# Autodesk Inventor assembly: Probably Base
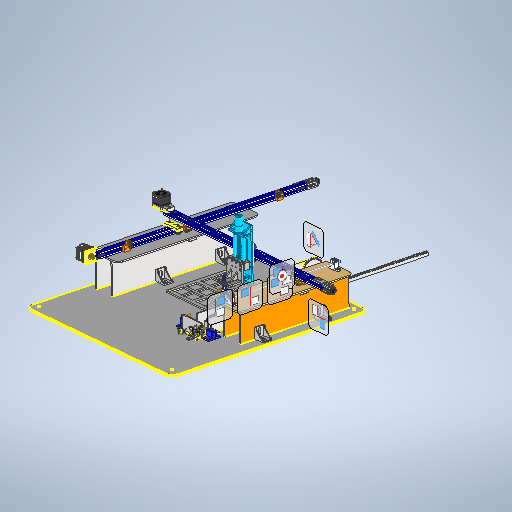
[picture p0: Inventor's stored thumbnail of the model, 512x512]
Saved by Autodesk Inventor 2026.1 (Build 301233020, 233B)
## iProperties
Created: 2026-10
Part Number: Probably Base
Document SubType Name: Assembly
Designer: hp
Author: hp
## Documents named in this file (53)
- C:\Users\hp\Documents\Inventor\DOM1_CartesianRobot\Probably Base.iam
- C:\Users\hp\Documents\Inventor\DOM1_CartesianRobot\StorageArea.ipt
- C:\Users\hp\Documents\Inventor\DOM1_CartesianRobot\BigBase.ipt
- C:\Users\hp\Documents\Inventor\DOM1_CartesianRobot\Side Wall Support.ipt
- C:\Users\hp\Documents\Inventor\DOM1_CartesianRobot\Belt Support.ipt
- C:\Users\hp\Documents\Inventor\DOM1_CartesianRobot\Assieme_guida_2020_nema.iam
- C:\Users\hp\Documents\Inventor\DOM1_CartesianRobot\Assieme_guida_2020_nema - Copy.iam
- C:\Users\hp\Documents\Inventor\DOM1_CartesianRobot\aluminum rod.ipt
- C:\Users\hp\Documents\Inventor\DOM1_CartesianRobot\color_sensor_holder.iam
- C:\Users\hp\Documents\Inventor\DOM1_CartesianRobot\reciever_wall.ipt
- C:\Users\hp\Documents\Inventor\DOM1_CartesianRobot\laser_assembly.iam
- C:\Users\hp\Documents\Inventor\DOM1_CartesianRobot\laser_detector.iam
- C:\Users\hp\Documents\Inventor\DOM1_CartesianRobot\piatto.ipt
- C:\Users\hp\Documents\Inventor\DOM1_CartesianRobot\z axis screw.iam
- C:\Users\hp\Documents\Inventor\DOM1_CartesianRobot\z_Bearing_Housing_Assembly.iam
- C:\Users\hp\Documents\Inventor\DOM1_CartesianRobot\tool_mout_assembly.iam
- C:\Users\hp\Documents\Inventor\DOM1_CartesianRobot\Side Wall Support 2.ipt
- C:\Users\hp\Documents\Inventor\DOM1_CartesianRobot\filler.ipt
- C:\Users\hp\Documents\Inventor\DOM1_CartesianRobot\L-Bracket.ipt
- C:\Users\hp\Documents\Inventor\DOM1_CartesianRobot\Belt Support_v2.ipt
- C:\Users\hp\Documents\Inventor\DOM1_CartesianRobot\8mm_Railclamp.ipt
- C:\Users\hp\Documents\Inventor\DOM1_CartesianRobot\SC8UU Linear Rail Bearing v5.ipt
- C:\Users\hp\Documents\Inventor\Content Center Files\R2026\en-US\ISO 4762(2)\ISO 4762 - M5 x 20ISO.ipt
- C:\Users\hp\Documents\Inventor\Content Center Files\R2026\en-US\ISO 7041\ISO 7041 - M5 - ISO.ipt
- C:\Users\hp\Documents\Inventor\DOM1_CartesianRobot\4040 Corner Bracket Right Angle L Shape.ipt
- C:\Users\hp\Documents\Inventor\Content Center Files\R2026\en-US\ISO 4762(2)\ISO 4762 - M6 x 20ISO.ipt
- C:\Users\hp\Documents\Inventor\Content Center Files\R2026\en-US\ISO 7041\ISO 7041 - M6 - ISO.ipt
- C:\Users\hp\Documents\Inventor\Content Center Files\R2026\en-US\JIS B 1111(2)\JIS B 1111 - M3x40(2).ipt
- C:\Users\hp\Documents\Inventor\DOM1_CartesianRobot\2020 M3.ipt
- C:\Users\hp\Documents\Inventor\Content Center Files\R2026\en-US\ISO 4017(1)\ISO 4017 - M4 x 35 - ISO.ipt
- C:\Users\hp\Documents\Inventor\DOM1_CartesianRobot\2020 M4 (1).ipt
- C:\Users\hp\Documents\Inventor\Content Center Files\R2026\en-US\ISO 4032(2)\ISO 4032 - M4 - ISO.ipt
- C:\Users\hp\Documents\Inventor\DOM1_CartesianRobot\Side Wall Support_v1_B.ipt
- C:\Users\hp\Documents\Inventor\DOM1_CartesianRobot\Side Wall Support 2 (B).ipt
- C:\Users\hp\Documents\Inventor\Content Center Files\R2026\en-US\ISO 4035(2)\ISO 4035 - M4 - ISO.ipt
- C:\Users\hp\Documents\Inventor\DOM1_CartesianRobot\color_sensor_holder_top.ipt
- C:\Users\hp\Documents\Inventor\DOM1_CartesianRobot\L298N Motor Driver.iam
- C:\Users\hp\Documents\Inventor\DOM1_CartesianRobot\Feeder Side Wall.ipt
- C:\Users\hp\Documents\Inventor\DOM1_CartesianRobot\pusher_support.ipt
- C:\Users\hp\Documents\Inventor\DOM1_CartesianRobot\pusher_pinion.ipt
- C:\Users\hp\Documents\Inventor\DOM1_CartesianRobot\pusher_punch.ipt
- C:\Users\hp\Documents\Inventor\DOM1_CartesianRobot\feeder_rack.ipt
- C:\Users\hp\Documents\Inventor\DOM1_CartesianRobot\Control Box.iam
- C:\Users\hp\Documents\Inventor\DOM1_CartesianRobot\NewProject\Product\Base.ipt
- C:\Users\hp\Documents\Inventor\DOM1_CartesianRobot\NewProject\Product\Lid.ipt
- C:\Users\hp\Documents\Inventor\DOM1_CartesianRobot\L-Bracket_3gneh.ipt
- C:\Users\hp\Documents\Inventor\Content Center Files\R2026\en-US\ISO 7045  H\ISO 7045 - M4 x 14_ - 4.8 - H - ISO.ipt
- C:\Users\hp\Documents\Inventor\DOM1_CartesianRobot\ColorSensorBottomPlate.ipt
- C:\Users\hp\Documents\Inventor\Content Center Files\R2026\en-US\ISO 7045  H\ISO 7045 - M4 x 35_ - 4.8 - H - ISO.ipt
- C:\Users\hp\Documents\Inventor\Content Center Files\R2026\en-US\ISO 7091\ISO 7091 - ST 4 - 100 HV.ipt
- C:\Users\hp\Documents\Inventor\DOM1_CartesianRobot\DC Motor Gearbox\DC Motor Gearbox\DC Motor Gearbox.iam
- C:\Users\hp\Documents\Inventor\Content Center Files\R2026\en-US\ISO 7045  H\ISO 7045 - M3 x 4_ - 4.8 - H - ISO.ipt
- C:\Users\hp\Documents\Inventor\Content Center Files\R2026\en-US\ISO 4035(2)\ISO 4035 - M3 - ISO.ipt
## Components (106 placed, 52 different names)
1. StorageArea:1 — Mate:1, Mate:690, Mate:691
2. BigBase:1 — Mate:1, Flush:17, Mate:40, Mate:41, Flush:22, Mate:62, Mate:64, Flush:23, Mate:66, Mate:67, Flush:24, Mate:70, Flush:27, Mate:119, Mate:121, Mate:123, Mate:125, Mate:132, Mate:133, Mate:134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
3. Assieme_guida_2020_nema:1 [sub-assembly] — Flush:9, Slider:1, Mate:75, Mate:76
4. Side Wall Support:1 — Mate:16, Flush:5, Flush:22, Mate:62, Mate:118, Mate:120, Mate:122, Mate:124, Mate:182, Flush:41, Mate:696
5. Side Wall Support_v1_B:1 — Mate:64, Flush:23, Flush:32, Mate:130, Mate:131, Mate:136, Mate:137, Mate:186, Mate:697
6. Belt Support:1 — Mate:16, Flush:5, Flush:9, Mate:75, Mate:76, Flush:32, Mate:183, Mate:188
7. Belt Support_v2:1 — Mate:68, Flush:25, Mate:91, Flush:35, Mate:92, Flush:36, Flush:37, Angle:1, Mate:192, Mate:196, Flush:62
8. Assieme_guida_2020_nema - Copy:1 [sub-assembly] — Mate:50, Slider:2, Mate:52, Flush:33, Flush:39, Mate:166, Mate:167, Angle:2, Angle:3, Mate:174, Mate:175, Angle:4, Angle:5
9. color_sensor_holder:1 [sub-assembly] — Mate:829, Flush:84, Flush:85, Flush:86
10. reciever_wall:1 — Flush:17, Mate:786, Flush:81, Mate:807, Mate:809, Mate:810, Mate:811
11. laser_assembly:1 [sub-assembly]
12. laser_detector:1 [sub-assembly] — Mate:41, Flush:82, Mate:811, Mate:816, Mate:818, Mate:824, Mate:826
13. piatto:1 — Slider:1, Mate:50, Mate:52, Mate:79, Flush:30, Flush:31, Mate:171, Mate:173
14. piatto:2 — Mate:48, Slider:2, Mate:71, Mate:72, Mate:117, Mate:161
15. z_Bearing_Housing_Assembly:1 [sub-assembly] — Mate:54, Mate:55, Mate:56, Mate:73, Mate:74, Mate:538, Mate:546, Mate:547, Mate:549, Mate:551, Mate:553
16. tool_mout_assembly:1 [sub-assembly] — Mate:54, Mate:55, Mate:56, Mate:539, Mate:540, Mate:541, Mate:542, Mate:543, Mate:544, Mate:545, Mate:548, Mate:550, Mate:552
17. Side Wall Support 2:1 — Mate:66, Mate:67, Flush:24, Mate:68, Flush:25, Mate:141, Mate:142, Mate:144, Mate:147, Mate:190, Flush:62, Flush:63
18. Side Wall Support 2 (B):1 — Mate:70, Flush:27, Mate:150, Mate:151, Mate:155, Mate:157, Mate:194, Flush:64, Mate:698
19. filler:1 — Mate:79, Flush:30, Flush:31, Flush:33, Mate:170, Mate:172
20. 8mm_Railclamp:1 — Mate:91, Flush:35, Mate:93, Flush:36, Mate:94, Flush:38
21. 8mm_Railclamp:2 — Mate:92, Mate:93, Flush:37
22. aluminum rod:1 — Mate:94, Flush:38, Mate:95
23. SC8UU Linear Rail Bearing v5:1 — Mate:95, Angle:1, Flush:39, Mate:162, Mate:163, Mate:164, Mate:165
24. ISO 4762 M5 x 20:1 — Mate:114, Mate:115
25. ISO 7041 M5:1 — Mate:116, Mate:117
26. 4040 Corner Bracket Right Angle L Shape:1 — Mate:118, Mate:119, Mate:126, Mate:178
27. 4040 Corner Bracket Right Angle L Shape:2 — Mate:120, Mate:121, Mate:127, Mate:178, Mate:694
28. 4040 Corner Bracket Right Angle L Shape:3 — Mate:122, Mate:123, Mate:126
29. 4040 Corner Bracket Right Angle L Shape:4 — Mate:124, Mate:125, Mate:127
30. 4040 Corner Bracket Right Angle L Shape:5 — Mate:135, Mate:137
31. 4040 Corner Bracket Right Angle L Shape:6 — Mate:134, Mate:136, Mate:179, Mate:695
32. 4040 Corner Bracket Right Angle L Shape:7 — Mate:130, Mate:133
33. 4040 Corner Bracket Right Angle L Shape:8 — Mate:131, Mate:132, Mate:179
34. 4040 Corner Bracket Right Angle L Shape:9 — Mate:140, Mate:141
35. 4040 Corner Bracket Right Angle L Shape:10 — Mate:142, Mate:143, Mate:180
36. 4040 Corner Bracket Right Angle L Shape:11 — Mate:144, Mate:145
37. 4040 Corner Bracket Right Angle L Shape:12 — Mate:146, Mate:147, Mate:180, Flush:63, Mate:694
38. 4040 Corner Bracket Right Angle L Shape:13 — Mate:154, Mate:155, Mate:181, Flush:64, Mate:695
39. 4040 Corner Bracket Right Angle L Shape:14 — Mate:156, Mate:157
40. 4040 Corner Bracket Right Angle L Shape:15 — Mate:150, Mate:153, Mate:181
41. 4040 Corner Bracket Right Angle L Shape:16 — Mate:151, Mate:152
42. ISO 4762 M6 x 20:1 — Mate:158, Mate:159
43. ISO 7041 M6:1 — Mate:160, Mate:161
44. JIS B 1111 M3x40:1 — Mate:162, Mate:163, Mate:168
45. JIS B 1111 M3x40:2 — Mate:164, Mate:165, Mate:169
46. 2020 M3:1 — Mate:166, Angle:2, Mate:168
47. 2020 M3:2 — Mate:167, Angle:3, Mate:169
48. ISO 4017 M4 x 35:1 — Mate:170, Mate:171, Mate:176
49. ISO 4017 M4 x 35:2 — Mate:172, Mate:173, Mate:177
50. 2020 M4 (1):1 — Mate:174, Angle:4, Mate:176
51. 2020 M4 (1):2 — Mate:175, Angle:5, Mate:177
52. L-Bracket:5 — Mate:182, Mate:183, Mate:200, Flush:41
53. L-Bracket:8 — Mate:194, Mate:196, Mate:199, Mate:203
54. L-Bracket:10 — Mate:190, Mate:192, Mate:199
55. L-Bracket:12 — Mate:186, Mate:188, Mate:200, Mate:203
56. ISO 4017 M4 x 35:3 — Mate:538, Mate:539
57. ISO 4035 M4:1 — Mate:546, Mate:547
58. ISO 4017 M4 x 35:4 — Mate:540, Mate:541
59. ISO 4017 M4 x 35:5 — Mate:542, Mate:543
60. ISO 4017 M4 x 35:6 — Mate:544, Mate:545
61. ISO 4035 M4:2 — Mate:548, Mate:549
62. ISO 4035 M4:3 — Mate:550, Mate:551
63. ISO 4035 M4:4 — Mate:552, Mate:553
64. color_sensor_holder_top:1 — Mate:651, Mate:652, Mate:786, Flush:86, Flush:87, Flush:88
65. L298N Motor Driver:1 [sub-assembly]
66. Feeder Side Wall:1 — Mate:707, Mate:710, Mate:712, Mate:799, Mate:800, Mate:801, Mate:802
67. Feeder Side Wall:2 — Mate:708, Mate:709, Mate:711, Mate:795, Mate:798, Mate:803, Mate:804
68. pusher_punch:2 — Mate:772, Mate:773, Mate:774, Flush:77
69. pusher_support:2 — Mate:847, Mate:848, Flush:90, Angle:6, Mate:856, Mate:858
70. pusher_pinion:2 — Flush:69, Mate:848, Mate:849, Mate:850, Flush:89
71. feeder_rack:1 — Mate:771, Flush:69, Mate:772, Mate:774, Flush:77, Flush:83
72. Control Box:1 [sub-assembly] — Mate:788
73. Base:1 — Mate:790
74. Lid:1 — Mate:789
75. L-Bracket_3gneh:1 — Mate:803, Mate:804
76. L-Bracket_3gneh:2 — Mate:801, Mate:802
77. L-Bracket_3gneh:4 — Mate:795, Mate:798
78. L-Bracket_3gneh:5 — Mate:799, Mate:800
79. L-Bracket_3gneh:6 — Mate:807, Mate:808
80. ISO 7045 H M4 x 14 - 4.8 - H:2 — Mate:812, Mate:813
81. ISO 4035 M4:5 — Mate:820, Mate:821
82. ISO 7045 H M4 x 14 - 4.8 - H:3 — Mate:814, Mate:815
83. ISO 7045 H M4 x 14 - 4.8 - H:4 — Mate:816, Mate:817
84. ISO 7045 H M4 x 14 - 4.8 - H:5 — Mate:818, Mate:819
85. ISO 4035 M4:6 — Mate:822, Mate:823
86. ISO 4035 M4:7 — Mate:824, Mate:825
87. ISO 4035 M4:8 — Mate:826, Mate:827
88. ColorSensorBottomPlate:1
89. ISO 7045 H M4 x 35 - 4.8 - H:1 — Mate:830, Mate:831
90. ISO 7091 ST 4 - 100 HV:1 — Mate:838, Mate:839
91. ISO 4032 M4:64
92. ISO 7045 H M4 x 35 - 4.8 - H:2 — Mate:832, Mate:833
93. ISO 7045 H M4 x 35 - 4.8 - H:3 — Mate:834, Mate:835
94. ISO 7045 H M4 x 35 - 4.8 - H:4 — Mate:836, Mate:837
95. ISO 7091 ST 4 - 100 HV:2 — Mate:840, Mate:841
96. ISO 7091 ST 4 - 100 HV:3 — Mate:842, Mate:843
97. ISO 7091 ST 4 - 100 HV:4 — Mate:844, Mate:845
98. ISO 4032 M4:65
99. ISO 4032 M4:66
100. ISO 4032 M4:67
101. DC Motor Gearbox:1 [sub-assembly]
102. ISO 7045 H M3 x 4 - 4.8 - H:1 — Mate:851, Mate:852
103. ISO 4035 M3:1 — Mate:855, Mate:856
104. ISO 7045 H M3 x 4 - 4.8 - H:2 — Mate:853, Mate:854
105. ISO 4035 M3:2 — Mate:857, Mate:858
106. z axis screw:1 [sub-assembly]
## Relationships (239: Mate 198, Flush 33, Angle 6, TranslationJoint 2)
- Mate:1: StorageArea:1 ↔ BigBase:1
- Mate:16: Side Wall Support:1 ↔ Belt Support:1
- Flush:5: Side Wall Support:1 ↔ Belt Support:1
- Flush:9: Assieme_guida_2020_nema:1 ↔ Belt Support:1
- Flush:17: BigBase:1 ↔ reciever_wall:1
- Mate:40: BigBase:1
- Mate:41: BigBase:1 ↔ laser_detector:1
- Slider:1 [TranslationJoint]: Assieme_guida_2020_nema:1 ↔ piatto:1
- Mate:48: piatto:2
- Mate:50: Assieme_guida_2020_nema - Copy:1 ↔ piatto:1
- Slider:2 [TranslationJoint]: Assieme_guida_2020_nema - Copy:1 ↔ piatto:2
- Mate:52: Assieme_guida_2020_nema - Copy:1 ↔ piatto:1
- Mate:54: z_Bearing_Housing_Assembly:1 ↔ tool_mout_assembly:1
- Mate:55: z_Bearing_Housing_Assembly:1 ↔ tool_mout_assembly:1
- Mate:56: z_Bearing_Housing_Assembly:1 ↔ tool_mout_assembly:1
- Flush:22: BigBase:1 ↔ Side Wall Support:1
- Mate:62: BigBase:1 ↔ Side Wall Support:1
- Mate:64: BigBase:1 ↔ Side Wall Support_v1_B:1
- Flush:23: BigBase:1 ↔ Side Wall Support_v1_B:1
- Mate:66: BigBase:1 ↔ Side Wall Support 2:1
- Mate:67: BigBase:1 ↔ Side Wall Support 2:1
- Flush:24: BigBase:1 ↔ Side Wall Support 2:1
- Mate:68: Belt Support_v2:1 ↔ Side Wall Support 2:1
- Flush:25: Belt Support_v2:1 ↔ Side Wall Support 2:1
- Mate:70: BigBase:1 ↔ Side Wall Support 2 (B):1
- Flush:27: BigBase:1 ↔ Side Wall Support 2 (B):1
- Mate:71: piatto:2
- Mate:72: piatto:2
- Mate:73: z_Bearing_Housing_Assembly:1
- Mate:74: z_Bearing_Housing_Assembly:1
- Mate:75: Assieme_guida_2020_nema:1 ↔ Belt Support:1
- Mate:76: Assieme_guida_2020_nema:1 ↔ Belt Support:1
- Mate:79: piatto:1 ↔ filler:1
- Flush:30: piatto:1 ↔ filler:1
- Flush:31: piatto:1 ↔ filler:1
- Flush:32: Side Wall Support_v1_B:1 ↔ Belt Support:1
- Flush:33: Assieme_guida_2020_nema - Copy:1 ↔ filler:1
- Mate:91: Belt Support_v2:1 ↔ 8mm_Railclamp:1
- Flush:35: Belt Support_v2:1 ↔ 8mm_Railclamp:1
- Mate:92: Belt Support_v2:1 ↔ 8mm_Railclamp:2
- Mate:93: 8mm_Railclamp:1 ↔ 8mm_Railclamp:2
- Flush:36: Belt Support_v2:1 ↔ 8mm_Railclamp:1
- Flush:37: Belt Support_v2:1 ↔ 8mm_Railclamp:2
- Mate:94: 8mm_Railclamp:1 ↔ aluminum rod:1
- Flush:38: 8mm_Railclamp:1 ↔ aluminum rod:1
- Mate:95: aluminum rod:1 ↔ SC8UU Linear Rail Bearing v5:1
- Angle:1: Belt Support_v2:1 ↔ SC8UU Linear Rail Bearing v5:1
- Mate:114: ISO 4762 M5 x 20:1
- Mate:115: ISO 4762 M5 x 20:1
- Mate:116: ISO 7041 M5:1
- Mate:117: piatto:2 ↔ ISO 7041 M5:1
- Mate:118: Side Wall Support:1 ↔ 4040 Corner Bracket Right Angle L Shape:1
- Mate:119: BigBase:1 ↔ 4040 Corner Bracket Right Angle L Shape:1
- Mate:120: Side Wall Support:1 ↔ 4040 Corner Bracket Right Angle L Shape:2
- Mate:121: BigBase:1 ↔ 4040 Corner Bracket Right Angle L Shape:2
- Mate:122: Side Wall Support:1 ↔ 4040 Corner Bracket Right Angle L Shape:3
- Mate:123: BigBase:1 ↔ 4040 Corner Bracket Right Angle L Shape:3
- Mate:124: Side Wall Support:1 ↔ 4040 Corner Bracket Right Angle L Shape:4
- Mate:125: BigBase:1 ↔ 4040 Corner Bracket Right Angle L Shape:4
- Mate:126: 4040 Corner Bracket Right Angle L Shape:1 ↔ 4040 Corner Bracket Right Angle L Shape:3
- Mate:127: 4040 Corner Bracket Right Angle L Shape:2 ↔ 4040 Corner Bracket Right Angle L Shape:4
- Mate:130: Side Wall Support_v1_B:1 ↔ 4040 Corner Bracket Right Angle L Shape:7
- Mate:131: Side Wall Support_v1_B:1 ↔ 4040 Corner Bracket Right Angle L Shape:8
- Mate:132: BigBase:1 ↔ 4040 Corner Bracket Right Angle L Shape:8
- Mate:133: BigBase:1 ↔ 4040 Corner Bracket Right Angle L Shape:7
- Mate:134: BigBase:1 ↔ 4040 Corner Bracket Right Angle L Shape:6
- Mate:135: BigBase:1 ↔ 4040 Corner Bracket Right Angle L Shape:5
- Mate:136: Side Wall Support_v1_B:1 ↔ 4040 Corner Bracket Right Angle L Shape:6
- Mate:137: Side Wall Support_v1_B:1 ↔ 4040 Corner Bracket Right Angle L Shape:5
- Mate:140: BigBase:1 ↔ 4040 Corner Bracket Right Angle L Shape:9
- Mate:141: Side Wall Support 2:1 ↔ 4040 Corner Bracket Right Angle L Shape:9
- Mate:142: Side Wall Support 2:1 ↔ 4040 Corner Bracket Right Angle L Shape:10
- Mate:143: BigBase:1 ↔ 4040 Corner Bracket Right Angle L Shape:10
- Mate:144: Side Wall Support 2:1 ↔ 4040 Corner Bracket Right Angle L Shape:11
- Mate:145: BigBase:1 ↔ 4040 Corner Bracket Right Angle L Shape:11
- Mate:146: BigBase:1 ↔ 4040 Corner Bracket Right Angle L Shape:12
- Mate:147: Side Wall Support 2:1 ↔ 4040 Corner Bracket Right Angle L Shape:12
- Mate:150: Side Wall Support 2 (B):1 ↔ 4040 Corner Bracket Right Angle L Shape:15
- Mate:151: Side Wall Support 2 (B):1 ↔ 4040 Corner Bracket Right Angle L Shape:16
- Mate:152: BigBase:1 ↔ 4040 Corner Bracket Right Angle L Shape:16
- Mate:153: BigBase:1 ↔ 4040 Corner Bracket Right Angle L Shape:15
- Mate:154: BigBase:1 ↔ 4040 Corner Bracket Right Angle L Shape:13
- Mate:155: Side Wall Support 2 (B):1 ↔ 4040 Corner Bracket Right Angle L Shape:13
- Mate:156: BigBase:1 ↔ 4040 Corner Bracket Right Angle L Shape:14
- Mate:157: Side Wall Support 2 (B):1 ↔ 4040 Corner Bracket Right Angle L Shape:14
- Mate:158: ISO 4762 M6 x 20:1
- Mate:159: ISO 4762 M6 x 20:1
- Mate:160: ISO 7041 M6:1
- Mate:161: piatto:2 ↔ ISO 7041 M6:1
- Flush:39: Assieme_guida_2020_nema - Copy:1 ↔ SC8UU Linear Rail Bearing v5:1
- Mate:162: SC8UU Linear Rail Bearing v5:1 ↔ JIS B 1111 M3x40:1
- Mate:163: SC8UU Linear Rail Bearing v5:1 ↔ JIS B 1111 M3x40:1
- Mate:164: SC8UU Linear Rail Bearing v5:1 ↔ JIS B 1111 M3x40:2
- Mate:165: SC8UU Linear Rail Bearing v5:1 ↔ JIS B 1111 M3x40:2
- Mate:166: Assieme_guida_2020_nema - Copy:1 ↔ 2020 M3:1
- Mate:167: Assieme_guida_2020_nema - Copy:1 ↔ 2020 M3:2
- Angle:2: Assieme_guida_2020_nema - Copy:1 ↔ 2020 M3:1
- Angle:3: Assieme_guida_2020_nema - Copy:1 ↔ 2020 M3:2
- Mate:168: JIS B 1111 M3x40:1 ↔ 2020 M3:1
- Mate:169: JIS B 1111 M3x40:2 ↔ 2020 M3:2
- Mate:170: filler:1 ↔ ISO 4017 M4 x 35:1
- Mate:171: piatto:1 ↔ ISO 4017 M4 x 35:1
- Mate:172: filler:1 ↔ ISO 4017 M4 x 35:2
- Mate:173: piatto:1 ↔ ISO 4017 M4 x 35:2
- Mate:174: Assieme_guida_2020_nema - Copy:1 ↔ 2020 M4 (1):1
- Mate:175: Assieme_guida_2020_nema - Copy:1 ↔ 2020 M4 (1):2
- Angle:4: Assieme_guida_2020_nema - Copy:1 ↔ 2020 M4 (1):1
- Angle:5: Assieme_guida_2020_nema - Copy:1 ↔ 2020 M4 (1):2
- Mate:176: ISO 4017 M4 x 35:1 ↔ 2020 M4 (1):1
- Mate:177: ISO 4017 M4 x 35:2 ↔ 2020 M4 (1):2
- Mate:178: 4040 Corner Bracket Right Angle L Shape:1 ↔ 4040 Corner Bracket Right Angle L Shape:2
- Mate:179: 4040 Corner Bracket Right Angle L Shape:6 ↔ 4040 Corner Bracket Right Angle L Shape:8
- Mate:180: 4040 Corner Bracket Right Angle L Shape:10 ↔ 4040 Corner Bracket Right Angle L Shape:12
- Mate:181: 4040 Corner Bracket Right Angle L Shape:13 ↔ 4040 Corner Bracket Right Angle L Shape:15
- Mate:182: Side Wall Support:1 ↔ L-Bracket:5
- Mate:183: Belt Support:1 ↔ L-Bracket:5
- Mate:186: Side Wall Support_v1_B:1 ↔ L-Bracket:12
- Mate:188: Belt Support:1 ↔ L-Bracket:12
- Mate:190: Side Wall Support 2:1 ↔ L-Bracket:10
- Mate:192: Belt Support_v2:1 ↔ L-Bracket:10
- Mate:194: Side Wall Support 2 (B):1 ↔ L-Bracket:8
- Mate:196: Belt Support_v2:1 ↔ L-Bracket:8
- Mate:199: L-Bracket:8 ↔ L-Bracket:10
- Mate:200: L-Bracket:5 ↔ L-Bracket:12
- Mate:203: L-Bracket:8 ↔ L-Bracket:12
- Flush:41: Side Wall Support:1 ↔ L-Bracket:5
- Mate:538: z_Bearing_Housing_Assembly:1 ↔ ISO 4017 M4 x 35:3
- Mate:539: tool_mout_assembly:1 ↔ ISO 4017 M4 x 35:3
- Mate:540: tool_mout_assembly:1 ↔ ISO 4017 M4 x 35:4
- Mate:541: tool_mout_assembly:1 ↔ ISO 4017 M4 x 35:4
- Mate:542: tool_mout_assembly:1 ↔ ISO 4017 M4 x 35:5
- Mate:543: tool_mout_assembly:1 ↔ ISO 4017 M4 x 35:5
- Mate:544: tool_mout_assembly:1 ↔ ISO 4017 M4 x 35:6
- Mate:545: tool_mout_assembly:1 ↔ ISO 4017 M4 x 35:6
- Mate:546: z_Bearing_Housing_Assembly:1 ↔ ISO 4035 M4:1
- Mate:547: z_Bearing_Housing_Assembly:1 ↔ ISO 4035 M4:1
- Mate:548: tool_mout_assembly:1 ↔ ISO 4035 M4:2
- Mate:549: z_Bearing_Housing_Assembly:1 ↔ ISO 4035 M4:2
- Mate:550: tool_mout_assembly:1 ↔ ISO 4035 M4:3
- Mate:551: z_Bearing_Housing_Assembly:1 ↔ ISO 4035 M4:3
- Mate:552: tool_mout_assembly:1 ↔ ISO 4035 M4:4
- Mate:553: z_Bearing_Housing_Assembly:1 ↔ ISO 4035 M4:4
- Mate:651: BigBase:1 ↔ color_sensor_holder_top:1
- Mate:652: BigBase:1 ↔ color_sensor_holder_top:1
- Mate:690: StorageArea:1 ↔ BigBase:1
- Mate:691: StorageArea:1 ↔ BigBase:1
- Flush:62: Belt Support_v2:1 ↔ Side Wall Support 2:1
- Flush:63: Side Wall Support 2:1 ↔ 4040 Corner Bracket Right Angle L Shape:12
- Flush:64: Side Wall Support 2 (B):1 ↔ 4040 Corner Bracket Right Angle L Shape:13
- Mate:694: 4040 Corner Bracket Right Angle L Shape:2 ↔ 4040 Corner Bracket Right Angle L Shape:12
- Mate:695: 4040 Corner Bracket Right Angle L Shape:6 ↔ 4040 Corner Bracket Right Angle L Shape:13
- Mate:696: BigBase:1 ↔ Side Wall Support:1
- Mate:697: BigBase:1 ↔ Side Wall Support_v1_B:1
- Mate:698: BigBase:1 ↔ Side Wall Support 2 (B):1
- Mate:707: BigBase:1 ↔ Feeder Side Wall:1
- Mate:708: BigBase:1 ↔ Feeder Side Wall:2
- Mate:709: BigBase:1 ↔ Feeder Side Wall:2
- Mate:710: BigBase:1 ↔ Feeder Side Wall:1
- Mate:711: BigBase:1 ↔ Feeder Side Wall:2
- Mate:712: BigBase:1 ↔ Feeder Side Wall:1
- Mate:771: BigBase:1 ↔ feeder_rack:1
- Flush:69: pusher_pinion:2 ↔ feeder_rack:1
- Mate:772: pusher_punch:2 ↔ feeder_rack:1
- Mate:773: BigBase:1 ↔ pusher_punch:2
- Mate:774: pusher_punch:2 ↔ feeder_rack:1
- Flush:77: pusher_punch:2 ↔ feeder_rack:1
- Mate:786: reciever_wall:1 ↔ color_sensor_holder_top:1
- Flush:81: BigBase:1 ↔ reciever_wall:1
- Mate:788: BigBase:1 ↔ Control Box:1
- Mate:789: BigBase:1 ↔ Lid:1
- Mate:790: BigBase:1 ↔ Base:1
- Mate:795: Feeder Side Wall:2 ↔ L-Bracket_3gneh:4
- Mate:798: Feeder Side Wall:2 ↔ L-Bracket_3gneh:4
- Mate:799: Feeder Side Wall:1 ↔ L-Bracket_3gneh:5
- Mate:800: Feeder Side Wall:1 ↔ L-Bracket_3gneh:5
- Mate:801: Feeder Side Wall:1 ↔ L-Bracket_3gneh:2
- Mate:802: Feeder Side Wall:1 ↔ L-Bracket_3gneh:2
- Mate:803: Feeder Side Wall:2 ↔ L-Bracket_3gneh:1
- Mate:804: Feeder Side Wall:2 ↔ L-Bracket_3gneh:1
- Mate:807: reciever_wall:1 ↔ L-Bracket_3gneh:6
- Mate:808: BigBase:1 ↔ L-Bracket_3gneh:6
- Mate:809: reciever_wall:1
- Mate:810: reciever_wall:1
- Flush:82: laser_detector:1
- Mate:811: reciever_wall:1 ↔ laser_detector:1
- Mate:812: ISO 7045 H M4 x 14 - 4.8 - H:2
- Mate:813: ISO 7045 H M4 x 14 - 4.8 - H:2
- Mate:814: ISO 7045 H M4 x 14 - 4.8 - H:3
- Mate:815: ISO 7045 H M4 x 14 - 4.8 - H:3
- Mate:816: laser_detector:1 ↔ ISO 7045 H M4 x 14 - 4.8 - H:4
- Mate:817: ISO 7045 H M4 x 14 - 4.8 - H:4
- Mate:818: laser_detector:1 ↔ ISO 7045 H M4 x 14 - 4.8 - H:5
- Mate:819: ISO 7045 H M4 x 14 - 4.8 - H:5
- Mate:820: ISO 4035 M4:5
- Mate:821: BigBase:1 ↔ ISO 4035 M4:5
- Mate:822: ISO 4035 M4:6
- Mate:823: BigBase:1 ↔ ISO 4035 M4:6
- Mate:824: laser_detector:1 ↔ ISO 4035 M4:7
- Mate:825: BigBase:1 ↔ ISO 4035 M4:7
- Mate:826: laser_detector:1 ↔ ISO 4035 M4:8
- Mate:827: BigBase:1 ↔ ISO 4035 M4:8
- Flush:83: BigBase:1 ↔ feeder_rack:1
- Mate:829: color_sensor_holder:1
- Flush:84: color_sensor_holder:1
- Flush:85: color_sensor_holder:1
- Flush:86: color_sensor_holder:1 ↔ color_sensor_holder_top:1
- Flush:87: color_sensor_holder_top:1
- Flush:88: color_sensor_holder_top:1
- Mate:830: ISO 7045 H M4 x 35 - 4.8 - H:1
- Mate:831: BigBase:1 ↔ ISO 7045 H M4 x 35 - 4.8 - H:1
- Mate:832: ISO 7045 H M4 x 35 - 4.8 - H:2
- Mate:833: BigBase:1 ↔ ISO 7045 H M4 x 35 - 4.8 - H:2
- Mate:834: ISO 7045 H M4 x 35 - 4.8 - H:3
- Mate:835: BigBase:1 ↔ ISO 7045 H M4 x 35 - 4.8 - H:3
- Mate:836: ISO 7045 H M4 x 35 - 4.8 - H:4
- Mate:837: BigBase:1 ↔ ISO 7045 H M4 x 35 - 4.8 - H:4
- Mate:838: ISO 7091 ST 4 - 100 HV:1
- Mate:839: ISO 7091 ST 4 - 100 HV:1
- Mate:840: ISO 7091 ST 4 - 100 HV:2
- Mate:841: ISO 7091 ST 4 - 100 HV:2
- Mate:842: ISO 7091 ST 4 - 100 HV:3
- Mate:843: ISO 7091 ST 4 - 100 HV:3
- Mate:844: ISO 7091 ST 4 - 100 HV:4
- Mate:845: ISO 7091 ST 4 - 100 HV:4
- Mate:847: BigBase:1 ↔ pusher_support:2
- Mate:848: pusher_support:2 ↔ pusher_pinion:2
- Mate:849: pusher_pinion:2
- Mate:850: pusher_pinion:2
- Flush:89: pusher_pinion:2
- Flush:90: pusher_support:2
- Angle:6: pusher_support:2
- Mate:851: ISO 7045 H M3 x 4 - 4.8 - H:1
- Mate:852: ISO 7045 H M3 x 4 - 4.8 - H:1
- Mate:853: ISO 7045 H M3 x 4 - 4.8 - H:2
- Mate:854: ISO 7045 H M3 x 4 - 4.8 - H:2
- Mate:855: ISO 4035 M3:1
- Mate:856: pusher_support:2 ↔ ISO 4035 M3:1
- Mate:857: ISO 4035 M3:2
- Mate:858: pusher_support:2 ↔ ISO 4035 M3:2
## Named parameters: d288_d286 = 0, d289_d286 = 0, d298_d289_d286 = 0, d299_d288_d286 = 0, d308_d289_d286 = 0, d309_d288_d286 = 0
